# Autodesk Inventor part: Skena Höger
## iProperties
Shininess: 64.0
Angle Display Precision: 2
Document Length Units: 11269
Document Angle Units: 11279
Document Time Units: 11290
Document Mass Units: 11283
Document Length Units Precision: 3
Document Angle Units Precision: 2
Created: 2001-12
Part Number: Skena Höger
Material: Steel, Mild
Document SubType Name: Modeling
Designer: Tobben
Density: 1 g/cm^3
Density: 0.0
Volumn: 0.0
Area: 0.0
PropertySet Name: Model Information
Control State: 0
Master: False
Checked Out: False
Author: Tobben
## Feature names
1. Derived Body1 [Tagging]
